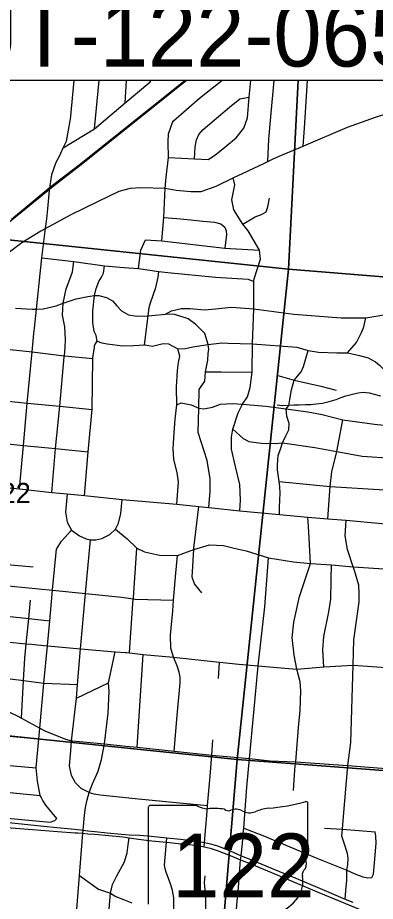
# Model space of a CAD drawing. Extents: x 0 to 34, y 0 to 22.
# Drawn here: x 7.157 to 7.896, y 16.358 to 18.183 of the extents above; entities that cross this region are included whole.
import ezdxf

# ---------------------------------------------------------------- set-up
doc = ezdxf.new("R2010")
doc.units = 0
for name, color, linetype in [('GM_X_City_Street', 7, 'Continuous'), ('GM_X_Corporation', 7, 'Continuous'), ('GM_X_County_Road', 7, 'Continuous'), ('GM_X_Minor_River', 7, 'Continuous'), ('GM_X_Rail_Line', 7, 'Continuous'), ('GM_X_Section_Text', 7, 'Continuous'), ('GM_X_State_Location', 7, 'Continuous'), ('GM_X_State_Route', 7, 'Continuous'), ('GM_X_State_Shield', 7, 'Continuous'), ('SH_Text', 7, 'Continuous')]:
    doc.layers.add(name, color=color, linetype=linetype)

msp = doc.modelspace()

# ---------------------------------------------------------------- linework, layer by layer
at = {"layer": 'GM_X_City_Street'}
for p, q in [((7.3155, 17.9528), (7.3251, 18.0529)), ((7.3789, 18.0069), (7.3817, 18.0529)), ((7.4297, 18.0492), (7.4326, 18.0529)), ((7.6941, 17.4438), (7.7277, 17.4339)), ((7.3959, 16.9846), (7.403, 17.0873)), ((7.3879, 16.8711), (7.3901, 16.9021)), ((7.4041, 16.6762), (7.4164, 16.8677)), ((7.5714, 16.8182), (7.5739, 16.8518)), ((7.1295, 16.8188), (7.1641, 16.8145)), ((7.2786, 16.7779), (7.3445, 16.8093))]:
    msp.add_line(p, q, dxfattribs=at)
for points in [[(7.2512, 17.9136), (7.3155, 17.9528), (7.3789, 18.0069), (7.4297, 18.0492)], [(7.4683, 17.8936), (7.5223, 17.8911), (7.5501, 17.8899), (7.5617, 17.8964), (7.5772, 17.9092), (7.6079, 17.9347), (7.624, 17.9544), (7.6313, 17.9758), (7.6349, 18.0181), (7.6385, 18.0529)], [(7.4764, 17.9663), (7.4791, 17.9693), (7.5328, 18.0161), (7.5787, 18.0529)], [(7.6737, 17.8855), (7.6757, 17.9317), (7.6796, 17.978), (7.6865, 18.0529)], [(7.7467, 17.9176), (7.749, 17.9544), (7.7553, 18.0529)], [(7.5223, 17.8911), (7.5235, 17.9162), (7.5261, 17.9306), (7.5313, 17.9413), (7.5403, 17.9517), (7.5719, 17.9784), (7.5941, 17.9981), (7.6161, 18.0152), (7.6349, 18.0181)], [(7.4545, 17.7218), (7.459, 17.7699), (7.4613, 17.8308), (7.4634, 17.8535), (7.4683, 17.8936), (7.4677, 17.9252), (7.4682, 17.943), (7.4764, 17.9663)], [(7.645, 17.6413), (7.6453, 17.6434), (7.6582, 17.6838), (7.6567, 17.7028), (7.633, 17.7424), (7.6223, 17.7564), (7.6033, 17.786), (7.599, 17.8063), (7.6031, 17.827), (7.6057, 17.8372), (7.602, 17.8518)], [(7.6223, 17.7564), (7.6474, 17.7714), (7.6602, 17.776), (7.6699, 17.782), (7.6735, 17.7919), (7.6772, 17.8102)], [(7.459, 17.7699), (7.4859, 17.7677), (7.5146, 17.765), (7.5395, 17.7627), (7.5634, 17.7606), (7.5764, 17.7566), (7.585, 17.7502), (7.5879, 17.7423), (7.5881, 17.7348), (7.5849, 17.7066)], [(7.4064, 17.6645), (7.4114, 17.7024), (7.4207, 17.7237)], [(7.4207, 17.7237), (7.4545, 17.7218), (7.5849, 17.7066), (7.6567, 17.7028)], [(7.2071, 17.6866), (7.2733, 17.6789), (7.3366, 17.6705), (7.377, 17.6668), (7.4064, 17.6645), (7.4485, 17.6587), (7.4674, 17.6564), (7.5658, 17.6467), (7.6332, 17.6425), (7.6445, 17.6382)], [(7.2533, 17.4824), (7.2535, 17.4844), (7.2551, 17.5017), (7.2556, 17.5181), (7.2543, 17.5444), (7.2499, 17.5687), (7.2511, 17.5929), (7.2572, 17.623), (7.2648, 17.6429), (7.2702, 17.6575), (7.2733, 17.6789)], [(7.3166, 17.5068), (7.3212, 17.5145), (7.3189, 17.5264), (7.3152, 17.5345), (7.3123, 17.5533), (7.312, 17.5774), (7.3156, 17.6087), (7.3192, 17.6232), (7.3247, 17.6378), (7.3303, 17.6468), (7.3344, 17.6553), (7.3366, 17.6705)], [(7.4189, 17.5069), (7.4263, 17.5673), (7.4284, 17.584), (7.4312, 17.5936), (7.4424, 17.6255), (7.447, 17.6469), (7.4485, 17.6587)], [(7.616, 17.1642), (7.6171, 17.1865), (7.6161, 17.2187), (7.6061, 17.259), (7.5983, 17.2917), (7.5984, 17.3164), (7.6015, 17.3328), (7.6123, 17.3665), (7.6215, 17.3849), (7.6318, 17.4), (7.6372, 17.4193), (7.6412, 17.4509), (7.6416, 17.5094), (7.6448, 17.5811), (7.6445, 17.6382), (7.645, 17.6413)], [(7.1528, 17.5831), (7.1869, 17.5809), (7.1957, 17.5805), (7.2098, 17.5817), (7.2364, 17.5877), (7.2511, 17.5929), (7.2779, 17.6018), (7.3021, 17.6072), (7.3156, 17.6087), (7.3244, 17.6088), (7.3407, 17.605), (7.3528, 17.5979), (7.3616, 17.5875), (7.3717, 17.5772), (7.3861, 17.5688), (7.4034, 17.566), (7.4263, 17.5673), (7.4341, 17.568), (7.4623, 17.5705), (7.4747, 17.5776), (7.4953, 17.5821), (7.513, 17.5819), (7.5431, 17.5791), (7.5654, 17.5814), (7.5984, 17.5847), (7.6448, 17.5811)], [(7.5518, 17.1711), (7.5545, 17.2049), (7.5548, 17.2304), (7.5483, 17.2683), (7.5296, 17.3263), (7.5308, 17.3764), (7.5318, 17.4147), (7.5437, 17.432), (7.5451, 17.4514), (7.5495, 17.4757), (7.5504, 17.4889), (7.5517, 17.4984), (7.5504, 17.5077), (7.5435, 17.5302), (7.5248, 17.5494), (7.5093, 17.5608), (7.4818, 17.5694), (7.4623, 17.5705)], [(7.6448, 17.5811), (7.727, 17.5704), (7.8249, 17.5627), (7.8762, 17.563), (7.9674, 17.5779), (8.0044, 17.5858)], [(7.8378, 17.4908), (7.8566, 17.5118), (7.8667, 17.5329), (7.8719, 17.5445), (7.8762, 17.563)], [(7.3212, 17.5145), (7.3307, 17.5115), (7.342, 17.509), (7.374, 17.5048), (7.3965, 17.5054), (7.4189, 17.5069), (7.4204, 17.507), (7.4352, 17.5042), (7.4575, 17.5099), (7.4687, 17.5091), (7.4875, 17.4986), (7.5034, 17.4997), (7.5189, 17.5027), (7.5504, 17.5077), (7.5786, 17.5112), (7.591, 17.5105), (7.6416, 17.5094)], [(7.2949, 17.1958), (7.3026, 17.2862), (7.3109, 17.3735), (7.312, 17.4786), (7.3121, 17.4801), (7.3154, 17.5021), (7.3155, 17.5051), (7.3166, 17.5068)], [(7.4859, 17.1781), (7.4894, 17.2246), (7.4864, 17.2433), (7.4794, 17.2707), (7.478, 17.2934), (7.48, 17.3251), (7.482, 17.3538), (7.4854, 17.3835), (7.4847, 17.4198), (7.4874, 17.4539), (7.4891, 17.4705), (7.4921, 17.4839), (7.4875, 17.4986)], [(7.6416, 17.5094), (7.7334, 17.5024), (7.7566, 17.4952), (7.7784, 17.492), (7.816, 17.4904), (7.8378, 17.4908), (7.863, 17.4851), (7.8811, 17.4801), (7.8961, 17.4717), (7.9039, 17.4651), (7.915, 17.4541)], [(7.2275, 17.2025), (7.2354, 17.2932), (7.2439, 17.3802), (7.2533, 17.4824)], [(7.7002, 17.2937), (7.7039, 17.3047), (7.7111, 17.3195), (7.7171, 17.3316), (7.7178, 17.3446), (7.7129, 17.3599), (7.7117, 17.375), (7.7169, 17.3822), (7.7189, 17.394), (7.7222, 17.4143), (7.7277, 17.4339), (7.7426, 17.4511), (7.7471, 17.4627), (7.7566, 17.4952)], [(7.5451, 17.4514), (7.5771, 17.4512), (7.6412, 17.4509)], [(6.8087, 17.431), (6.8187, 17.4238), (6.8266, 17.4205), (6.8329, 17.4183), (6.8393, 17.4169), (6.8578, 17.4156), (6.8864, 17.4151), (6.954, 17.4088), (7.0273, 17.4016), (7.1046, 17.3944), (7.1769, 17.3868), (7.2439, 17.3802), (7.3109, 17.3735)], [(7.7277, 17.4339), (7.7829, 17.4217), (7.815, 17.4137)], [(7.4854, 17.3835), (7.4947, 17.3871), (7.5155, 17.383), (7.5308, 17.3764), (7.5415, 17.3748), (7.559, 17.3784), (7.5761, 17.3843), (7.6008, 17.3863), (7.6215, 17.3849)], [(7.6215, 17.3849), (7.6693, 17.3808), (7.7117, 17.375), (7.7563, 17.3685), (7.7855, 17.3636), (7.8287, 17.3525), (7.8942, 17.3432), (7.9395, 17.3388)], [(7.7976, 17.148), (7.8021, 17.2148), (7.8058, 17.2448), (7.816, 17.2866), (7.8287, 17.3525)], [(7.6015, 17.3328), (7.6226, 17.314), (7.6344, 17.3077), (7.6595, 17.3044), (7.6885, 17.3037), (7.7039, 17.3047), (7.7707, 17.2951), (7.816, 17.2866), (7.8684, 17.2773), (7.93, 17.2729), (7.9743, 17.2689), (8.0015, 17.2671), (8.0923, 17.2494), (8.0976, 17.2485), (8.1596, 17.2476), (8.1867, 17.2446), (8.22, 17.2419), (8.2549, 17.2385), (8.2877, 17.2326)], [(6.8777, 17.3284), (6.9462, 17.3222), (7.0191, 17.3144), (7.0961, 17.3071), (7.1688, 17.2995), (7.2354, 17.2932), (7.3026, 17.2862)], [(7.6977, 17.1566), (7.6978, 17.1703), (7.6981, 17.1877), (7.6988, 17.2), (7.6981, 17.2137), (7.6971, 17.2253), (7.6936, 17.249), (7.6939, 17.2596), (7.6951, 17.2789), (7.7002, 17.2937)], [(7.6971, 17.2253), (7.8021, 17.2148), (7.9147, 17.2081), (7.9611, 17.2049), (8.0073, 17.2004), (8.0715, 17.1967), (8.0934, 17.1943), (8.169, 17.188), (8.1995, 17.1837), (8.2264, 17.182), (8.2817, 17.1774), (8.293, 17.1775), (8.3088, 17.1758), (8.3195, 17.1713)], [(7.2594, 17.1994), (7.2559, 17.1615), (7.2591, 17.1411), (7.2685, 17.1248), (7.2846, 17.1125), (7.2987, 17.1063), (7.3075, 17.1045), (7.3186, 17.1044), (7.3305, 17.1072), (7.3473, 17.1157), (7.3588, 17.1266), (7.3652, 17.1387), (7.3702, 17.1588), (7.3729, 17.188)], [(7.5374, 16.995), (7.5223, 17.0135), (7.5172, 17.0277), (7.5206, 17.0848), (7.5208, 17.0872), (7.5311, 17.1733)], [(7.7268, 16.5873), (7.7285, 16.6185), (7.7302, 16.6377), (7.7311, 16.646), (7.7371, 16.7174), (7.7407, 16.752), (7.7419, 16.7925), (7.7404, 16.8112), (7.7333, 16.8373), (7.7282, 16.8662), (7.7236, 16.903), (7.7272, 16.9347), (7.7393, 16.9878), (7.7614, 17.0557), (7.759, 17.108), (7.7573, 17.132), (7.7562, 17.1516)], [(7.8335, 16.3628), (7.8347, 16.3809), (7.8365, 16.4018), (7.837, 16.4225), (7.8385, 16.4338), (7.8395, 16.447), (7.8383, 16.4567), (7.8311, 16.4782), (7.8266, 16.4926), (7.8276, 16.5072), (7.8296, 16.5332), (7.8388, 16.6385), (7.8451, 16.686), (7.8497, 16.8461), (7.8515, 16.898), (7.8623, 16.9765), (7.8624, 16.994), (7.8613, 17.0107), (7.8526, 17.041), (7.8501, 17.0486), (7.8382, 17.0843), (7.8336, 17.1126), (7.8351, 17.1448)], [(7.2056, 16.573), (7.2034, 16.577), (7.198, 16.6066), (7.1952, 16.6336), (7.2006, 16.6935), (7.2026, 16.7159), (7.211, 16.8076), (7.2111, 16.8087), (7.2183, 16.8857), (7.2232, 16.9375), (7.2291, 17.0004), (7.2292, 17.0013), (7.237, 17.0851), (7.2474, 17.1018), (7.2685, 17.1248)], [(7.3588, 17.1266), (7.3832, 17.1065), (7.4021, 17.0878), (7.403, 17.0873), (7.4187, 17.0801), (7.4497, 17.0727), (7.4873, 17.0724), (7.5206, 17.0848), (7.5534, 17.0939), (7.5822, 17.093), (7.6042, 17.0875), (7.6292, 17.0819), (7.675, 17.0675), (7.7268, 17.0589), (7.7614, 17.0557), (7.8049, 17.0531), (7.8501, 17.0486), (7.9448, 17.0429), (7.9925, 17.0368)], [(7.3049, 16.583), (7.2884, 16.5912), (7.2762, 16.6027), (7.2682, 16.6179), (7.2641, 16.6381), (7.2665, 16.669), (7.2685, 16.6897), (7.2786, 16.7779), (7.2809, 16.8056), (7.287, 16.8798), (7.2973, 16.9937), (7.3075, 17.1045)], [(6.9693, 17.0684), (7.1129, 17.0558), (7.1189, 17.0553), (7.1196, 17.0552), (7.1893, 17.0487)], [(7.4801, 16.6684), (7.4866, 16.7417), (7.4927, 16.809), (7.4928, 16.8209), (7.4907, 16.8313), (7.4866, 16.8443), (7.4788, 16.8625), (7.4731, 16.8808), (7.4723, 16.9077), (7.4772, 16.9578), (7.479, 16.9801), (7.4837, 17.0358), (7.4873, 17.0724)], [(7.5958, 16.1486), (7.5973, 16.189), (7.6031, 16.2558), (7.606, 16.2979), (7.6085, 16.3338), (7.6105, 16.3582), (7.6131, 16.3871), (7.6175, 16.4441), (7.6188, 16.4522), (7.621, 16.4779), (7.6228, 16.4986), (7.6242, 16.5095), (7.6304, 16.5939), (7.6359, 16.653), (7.6444, 16.748), (7.6534, 16.8441), (7.6677, 16.9662), (7.675, 17.0675)], [(7.7895, 16.8421), (7.787, 16.8777), (7.789, 16.9048), (7.7998, 16.9557), (7.8039, 16.9822), (7.8046, 17.0221), (7.8049, 17.0531)], [(6.9883, 17.0222), (7.1154, 17.0116), (7.2291, 17.0004), (7.2973, 16.9937), (7.372, 16.9863), (7.3957, 16.9826), (7.3997, 16.9819), (7.479, 16.9801)], [(7.3901, 16.9021), (7.3957, 16.9826), (7.3959, 16.9846)], [(7.1646, 16.7365), (7.1692, 16.8139), (7.1719, 16.8599), (7.1748, 16.8899), (7.1799, 16.9422), (7.1835, 16.9797)], [(7.001, 16.9595), (7.1218, 16.9486), (7.1799, 16.9422), (7.2232, 16.9375)], [(7.0188, 16.901), (7.0927, 16.8978), (7.1748, 16.8899), (7.1859, 16.8888), (7.2174, 16.8858), (7.2183, 16.8857), (7.287, 16.8798), (7.3584, 16.8736), (7.38, 16.8718)], [(7.3364, 16.6832), (7.3436, 16.747), (7.3459, 16.7911), (7.3445, 16.8093), (7.3584, 16.8736)], [(7.38, 16.8718), (7.382, 16.8716), (7.3879, 16.8711), (7.4164, 16.8677), (7.4788, 16.8625), (7.5739, 16.8518), (7.6138, 16.8478), (7.6534, 16.8441), (7.7086, 16.8398), (7.7333, 16.8373), (7.7895, 16.8421), (7.8497, 16.8461), (7.8891, 16.843), (7.9267, 16.8401), (7.9612, 16.8375), (8.002, 16.8424), (8.0303, 16.8479), (8.0584, 16.8534), (8.0803, 16.8564), (8.1016, 16.8588), (8.1208, 16.857), (8.1403, 16.8489)], [(7.1641, 16.8145), (7.1692, 16.8139), (7.2111, 16.8087), (7.2809, 16.8056)], [(6.609, 16.7516), (6.6521, 16.7475), (6.6971, 16.7431), (6.7799, 16.7352), (6.8659, 16.7265), (6.9543, 16.7184), (6.9857, 16.7155), (7.0268, 16.7112), (7.1394, 16.6994), (7.2006, 16.6935), (7.2299, 16.6912)], [(6.6925, 16.6848), (6.7749, 16.6742), (6.8617, 16.6651), (6.9534, 16.6555), (6.9708, 16.6537), (7.0229, 16.649), (7.1952, 16.6336)], [(7.2915, 16.4987), (7.2921, 16.5053), (7.2953, 16.5358), (7.2969, 16.5518), (7.3002, 16.568), (7.3049, 16.583), (7.3116, 16.6005), (7.3232, 16.6266), (7.3299, 16.6509), (7.3364, 16.6832)], [(7.5423, 16.4708), (7.5429, 16.4799), (7.5456, 16.512), (7.5477, 16.5351), (7.5493, 16.556), (7.5543, 16.6165), (7.5579, 16.6602), (7.5602, 16.6915)], [(6.689, 16.6265), (6.7726, 16.6177), (6.8593, 16.6108), (6.9467, 16.602), (7.0074, 16.5962), (7.2034, 16.577)], [(7.2379, 16.5293), (7.215, 16.5564), (7.209, 16.5667), (7.2056, 16.573)], [(7.3049, 16.583), (7.3144, 16.5801), (7.3274, 16.578), (7.3997, 16.5706), (7.4627, 16.5643), (7.5493, 16.556)], [(6.9964, 16.5451), (7.0014, 16.5445), (7.1282, 16.5305), (7.2241, 16.5215), (7.2338, 16.5251), (7.2379, 16.5293)], [(7.6242, 16.5095), (7.6632, 16.494), (7.7747, 16.4475), (7.837, 16.4225), (7.8534, 16.4151), (7.8699, 16.4085), (7.8799, 16.4065), (7.8883, 16.4074)], [(7.7907, 16.5094), (7.8276, 16.5072), (7.8954, 16.502)], [(7.8883, 16.4074), (7.8918, 16.414), (7.8942, 16.4378), (7.8975, 16.4784), (7.8968, 16.4926), (7.8954, 16.502)], [(7.338, 16.1671), (7.3412, 16.2044), (7.3419, 16.2133), (7.3454, 16.3343), (7.3488, 16.3754), (7.3526, 16.393), (7.3619, 16.4107), (7.3778, 16.4395), (7.3833, 16.4584), (7.3855, 16.4746), (7.3871, 16.4896)], [(7.4652, 16.18), (7.467, 16.2014), (7.4795, 16.3462), (7.4797, 16.3653), (7.477, 16.3807), (7.4732, 16.3925), (7.4634, 16.4185), (7.4615, 16.4253), (7.4602, 16.4326), (7.4642, 16.4802), (7.4649, 16.4895)], [(7.2846, 16.4116), (7.3239, 16.3831), (7.3488, 16.3754), (7.3598, 16.3683), (7.3754, 16.3619), (7.3928, 16.3553)], [(7.5295, 16.1485), (7.5329, 16.1947), (7.5359, 16.2355), (7.5453, 16.3398), (7.5458, 16.367), (7.5431, 16.3968), (7.5439, 16.4111)]]:
    msp.add_lwpolyline(points, dxfattribs=at)
at = {"layer": 'GM_X_Corporation'}
for points in [[(7.7361, 18.0529), (7.7161, 17.6636), (6.6697, 17.7728), (6.7468, 18.7711), (7.7682, 18.6757), (7.7459, 18.2415)], [(7.7459, 18.2415), (7.7682, 18.6757), (8.8396, 18.6106), (8.7511, 17.5795), (7.7161, 17.6636), (7.7361, 18.0529)]]:
    msp.add_lwpolyline(points, dxfattribs=at)
for points in [[(6.6697, 17.7728), (7.7161, 17.6636), (7.6101, 16.6513), (6.5907, 16.7563)], [(7.7161, 17.6636), (8.7511, 17.5795), (8.6706, 16.571), (7.6101, 16.6513)], [(6.5907, 16.7563), (7.6101, 16.6513), (7.5243, 15.6293), (6.4956, 15.7207), (6.5104, 15.9318), (6.5598, 16.3771)], [(7.6101, 16.6513), (8.6706, 16.571), (8.5797, 15.5737), (7.5243, 15.6293)]]:
    msp.add_lwpolyline(points, close=True, dxfattribs=at)
at = {"layer": 'GM_X_County_Road'}
for p, q in [((7.602, 17.8518), (7.6655, 17.8817)), ((7.2071, 17.6866), (7.2143, 17.7473)), ((7.2705, 16.6895), (7.3364, 16.6832)), ((7.3364, 16.6832), (7.3802, 16.6787))]:
    msp.add_line(p, q, dxfattribs=at)
for points in [[(7.2657, 17.9696), (7.2663, 17.9724), (7.2738, 18.0529)], [(7.7476, 17.918), (7.8382, 17.9567), (7.8961, 17.9769), (7.9211, 17.9856), (7.991, 18.012), (8.0255, 18.0288), (8.0606, 18.0529)], [(7.2462, 17.903), (7.2512, 17.9136), (7.2581, 17.9279), (7.2622, 17.9504), (7.2657, 17.9696)], [(7.6655, 17.8817), (7.6737, 17.8855), (7.6835, 17.8901), (7.6969, 17.8964), (7.7467, 17.9176), (7.7476, 17.918)], [(7.2143, 17.7473), (7.2169, 17.767), (7.2194, 17.7879), (7.2225, 17.8256), (7.2279, 17.8586), (7.2368, 17.8844), (7.2433, 17.8968), (7.2462, 17.903)], [(7.2058, 17.7427), (7.2143, 17.7473), (7.2663, 17.7752), (7.3238, 17.8037), (7.3667, 17.8246), (7.3898, 17.8303), (7.4111, 17.8322), (7.4613, 17.8308), (7.4844, 17.8264), (7.5144, 17.8235), (7.5356, 17.8235), (7.5671, 17.835), (7.602, 17.8518)], [(7.1322, 17.6932), (7.1657, 17.7185), (7.2049, 17.7423), (7.2058, 17.7427)], [(7.1916, 17.5414), (7.1957, 17.5805), (7.2071, 17.6866)], [(7.1607, 17.2101), (7.1688, 17.2995), (7.1769, 17.3868), (7.1867, 17.4927), (7.1905, 17.5306), (7.1916, 17.5414)], [(7.0792, 17.5042), (7.1145, 17.5004), (7.1867, 17.4927), (7.2477, 17.485), (7.2535, 17.4844), (7.312, 17.4786)], [(6.8723, 17.2385), (6.9385, 17.2323), (7.0115, 17.2251), (7.0882, 17.2176), (7.1336, 17.2126), (7.1607, 17.2101), (7.2275, 17.2025), (7.2594, 17.1994), (7.2949, 17.1958), (7.3729, 17.188), (7.4859, 17.1781), (7.5311, 17.1733), (7.5518, 17.1711), (7.616, 17.1642), (7.6977, 17.1566), (7.7562, 17.1516), (7.7976, 17.148), (7.8351, 17.1448), (7.9089, 17.1384), (7.9991, 17.1306), (8.028, 17.1281)], [(7.0578, 16.7995), (7.0731, 16.7846), (7.099, 16.7677), (7.1429, 16.7473), (7.1545, 16.7419), (7.1646, 16.7365), (7.2026, 16.7159), (7.2131, 16.7103), (7.2557, 16.6928), (7.2685, 16.6897), (7.2705, 16.6895)], [(7.3802, 16.6787), (7.4041, 16.6762), (7.4801, 16.6684), (7.5579, 16.6602), (7.6349, 16.6531)], [(7.6349, 16.6531), (7.6359, 16.653), (7.6782, 16.6486), (7.7311, 16.646), (7.8388, 16.6385), (7.9181, 16.6321), (7.9694, 16.6276), (8.1209, 16.6175), (8.2084, 16.61), (8.3198, 16.6017), (8.4215, 16.5931), (8.4834, 16.5891), (8.5875, 16.5806), (8.6103, 16.578), (8.6616, 16.5734)], [(7.2672, 16.189), (7.2689, 16.2115), (7.2846, 16.4116), (7.2915, 16.4987)]]:
    msp.add_lwpolyline(points, dxfattribs=at)
at = {"layer": 'GM_X_Minor_River'}
msp.add_lwpolyline([(7.693, 17.3829), (7.704, 17.3819), (7.7162, 17.3828), (7.7272, 17.3829), (7.7386, 17.3834), (7.7515, 17.3839), (7.7621, 17.3841), (7.7731, 17.3854), (7.7864, 17.3866), (7.8002, 17.3898), (7.8147, 17.3944), (7.825, 17.3984), (7.8346, 17.4016), (7.8457, 17.4048), (7.8598, 17.4079), (7.8708, 17.4096), (7.8829, 17.4082), (7.8935, 17.4053), (7.9063, 17.402)], dxfattribs=at)
at = {"layer": 'GM_X_Rail_Line'}
for points in [[(6.753, 17.3856), (6.7634, 17.4003), (6.8116, 17.4684), (6.8513, 17.5139), (6.8825, 17.5465), (6.8987, 17.5617), (6.9235, 17.5818), (6.9432, 17.5988), (6.9753, 17.6267), (7.0552, 17.6911), (7.1453, 17.7653), (7.2266, 17.8322), (7.2855, 17.8771), (7.5051, 18.0529)], [(7.1441, 17.7667), (7.2254, 17.8337), (7.2843, 17.8786), (7.502, 18.0529)]]:
    msp.add_lwpolyline(points, dxfattribs=at)
at = {"layer": 'GM_X_State_Route'}
for p, q in [((7.2811, 16.4995), (7.2915, 16.4987)), ((7.2915, 16.4987), (7.3019, 16.4979))]:
    msp.add_line(p, q, dxfattribs=at)
for points in [[(6.6611, 16.5813), (6.6723, 16.5735), (6.6846, 16.5677), (6.6947, 16.5645), (6.7095, 16.5619), (6.7368, 16.5593), (6.7669, 16.5564), (6.7982, 16.5535), (6.8318, 16.5503), (6.8829, 16.5455), (6.9423, 16.5399), (6.9802, 16.5363), (7.0085, 16.5334), (7.0408, 16.5303), (7.0784, 16.5268), (7.1385, 16.5211), (7.1844, 16.5164), (7.2377, 16.5108), (7.2752, 16.5071), (7.2921, 16.5053), (7.3021, 16.504)], [(6.9882, 16.5248), (7.0143, 16.5221), (7.0755, 16.5164), (7.1347, 16.5109), (7.1874, 16.5066), (7.2394, 16.5023), (7.276, 16.4999), (7.2811, 16.4995)], [(7.3019, 16.4979), (7.3156, 16.4967), (7.3452, 16.4942), (7.3746, 16.4913), (7.3871, 16.4896)], [(7.3021, 16.504), (7.3161, 16.5021), (7.342, 16.4995), (7.3712, 16.497), (7.3873, 16.4957), (7.4096, 16.4947), (7.4325, 16.4927), (7.4649, 16.4895), (7.493, 16.4863), (7.5158, 16.484), (7.5305, 16.482), (7.5429, 16.4799), (7.5552, 16.4769), (7.5696, 16.4725), (7.5955, 16.4623), (7.6188, 16.4522), (7.6399, 16.4436), (7.6827, 16.4259), (7.7313, 16.4057), (7.7802, 16.3853), (7.8335, 16.3628), (7.8493, 16.3563)], [(7.3871, 16.4896), (7.4067, 16.4863), (7.4339, 16.4834), (7.4642, 16.4802), (7.4946, 16.4771), (7.5171, 16.4747), (7.5306, 16.4732), (7.5423, 16.4708), (7.5547, 16.4678), (7.5691, 16.4634), (7.5923, 16.4545), (7.6175, 16.4441), (7.6398, 16.4347), (7.6813, 16.4174), (7.7301, 16.3971), (7.7788, 16.3767), (7.8339, 16.3536), (7.8692, 16.3392), (7.8835, 16.3344), (7.8978, 16.3307), (7.9057, 16.3291), (7.9131, 16.3281), (7.9268, 16.3264), (7.9531, 16.3239)]]:
    msp.add_lwpolyline(points, dxfattribs=at)
at = {"layer": 'GM_X_State_Shield'}
for p, q in [((7.4268, 16.5523), (7.4268, 16.3522)), ((7.5266, 16.5558), (7.4301, 16.5558)), ((7.7564, 16.456), (7.7564, 16.5607)), ((7.7564, 16.4561), (7.7564, 16.456))]:
    msp.add_line(p, q, dxfattribs=at)
for centre, major_axis, start_param, end_param in [((7.4306, 16.5527), (0.00382, 0), 1.712693, 3.28349), ((7.5496, 16.579), (0.037, 0), 4.042523, 4.731795), ((7.5618, 16.4434), (0.133, 0), 1.404758, 1.657858), ((7.592, 16.5538), (0.0107, 0), 3.836095, 5.185415), ((7.6077, 16.5306), (0.0222, 0), 0.950623, 2.079405), ((7.6836, 16.4946), (0.0703, 0), 1.699011, 2.107814), ((7.639, 16.8286), (0.3495, 0), 4.814394, 5.042369), ((7.7527, 16.5611), (0.00367, 0), 6.141152, 7.989035), ((7.6364, 16.5624), (0.0267, 0), 4.081561, 5.145723), ((7.7525, 16.4556), (0.00393, 0), 5.05454, 6.418171), ((7.7555, 16.4483), (0.00568, 0), 1.883978, 3.671073), ((7.7194, 16.4351), (0.0341, 0), 5.934695, 6.695948), ((7.7695, 16.4122), (0.0248, 0), 2.387724, 3.262537), ((7.6586, 16.3989), (0.0874, 0), 5.101752, 6.440018)]:
    msp.add_ellipse(centre, major_axis=major_axis, ratio=0.8, start_param=start_param, end_param=end_param, dxfattribs=at)
at = {"layer": 'SH_Text'}
msp.add_lwpolyline([(8.27, 18.2419), (6.8929, 18.2419), (6.8929, 18.0533), (8.27, 18.0533)], close=True, dxfattribs=at)

# ---------------------------------------------------------------- texts
at = {"layer": 'GM_X_Section_Text'}
msp.add_text('22', height=0.04186, rotation=0, dxfattribs=at).set_placement((7.1219, 17.1803))
at = {"layer": 'GM_X_State_Location'}
for s in ['s', 'r']:
    msp.add_text(s, height=0.000189, dxfattribs=at).set_placement((7.5879, 16.4389))
msp.add_text('122', height=0.000189, rotation=0, dxfattribs=at).set_placement((7.521, 16.4252))
at = {"layer": 'GM_X_State_Shield'}
msp.add_text('122', height=0.13184, dxfattribs=at).set_placement((7.4758, 16.3663))
at = {"layer": 'SH_Text'}
msp.add_text('BUT-122-0650R', height=0.133892, dxfattribs=at).set_placement((6.909, 18.0817))

doc.saveas('drawing.dxf')
